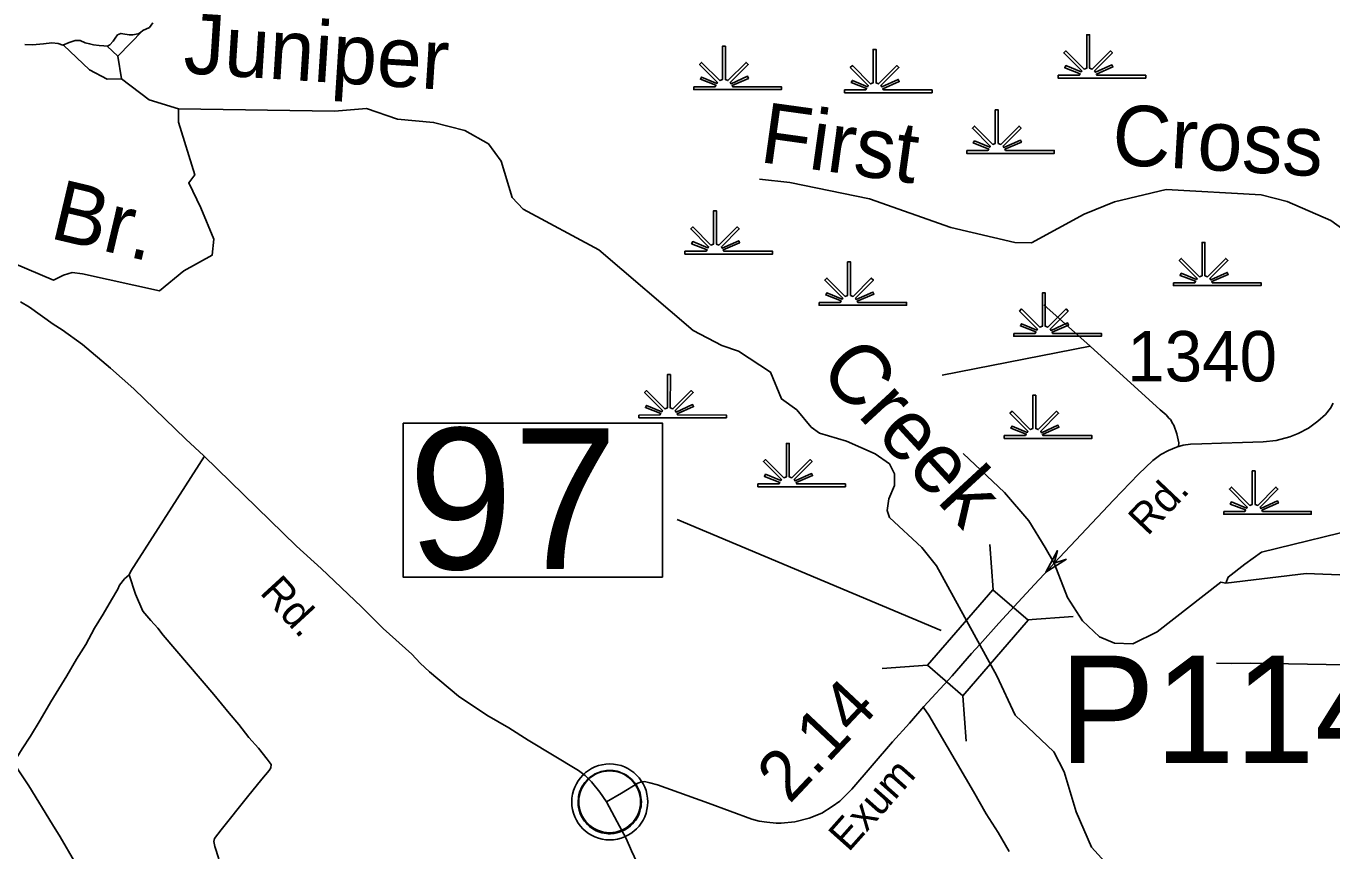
# Model space of a CAD drawing. Extents: x 2104537 to 2336408, y 34176 to 229611.
# Drawn here: x 2173826 to 2186795, y 134278 to 142470 of the extents above; entities that cross this region are included whole.
import ezdxf

# ---------------------------------------------------------------- set-up
doc = ezdxf.new("R2010")
doc.units = 0
for name, color, linetype in [('Exist Boundary Political CountyLine', 7, 'Continuous'), ('Exist Civil Demographics Community CELL', 7, 'Continuous'), ('Exist Hydrographic Creek Single Shore', 7, 'Continuous'), ('Exist Hydrographic Misc Water Feature', 7, 'Continuous'), ('Exist Hydrographic Pond Under 1500 Sq Ft', 7, 'Continuous'), ('Exist Hydrographic Swamp CELL', 7, 'Continuous'), ('Exist Road Non-System Type 51', 7, 'Continuous'), ('Exist Road Primary NC Structure Standard Bridge Number Label', 7, 'Continuous'), ('Exist Road Secondary Mileage Hundredths English Label', 7, 'Continuous'), ('Exist Road Secondary Structure Pipe Attributed CELL', 7, 'Continuous'), ('Exist Road Secondary Structure Pipe Number Label', 7, 'Continuous'), ('Exist Road Secondary Structure Standard Bridge CELL', 7, 'Continuous'), ('Exist Road Secondary Structure Standard Bridge Number Label', 7, 'Continuous'), ('Exist Road Secondary Type 51 Attributed', 7, 'Continuous'), ('Exist Road Secondary Type 51 Label', 7, 'Continuous'), ('Exist Road Secondary Type 51 Number Label', 7, 'Continuous'), ('Old_Level_32', 7, 'Continuous')]:
    doc.layers.add(name, color=color, linetype=linetype)

msp = doc.modelspace()

# ---------------------------------------------------------------- linework, layer by layer
at = {"layer": 'Exist Boundary Political CountyLine'}
msp.add_lwpolyline([(2173813, 142288), (2173888, 142285), (2174000, 142295), (2174081, 142304), (2174144, 142298), (2174191, 142279), (2174253, 142307), (2174312, 142326), (2174362, 142326), (2174412, 142304), (2174456, 142295), (2174494, 142285), (2174553, 142276), (2174597, 142273), (2174634, 142270), (2174659, 142285), (2174690, 142320), (2174712, 142351), (2174734, 142382), (2174768, 142398), (2174787, 142392), (2174850, 142382), (2174884, 142382), (2174940, 142392), (2174962, 142407), (2174984, 142426), (2175050, 142457), (2175084, 142501)], dxfattribs=at)
at = {"layer": 'Exist Civil Demographics Community CELL'}
msp.add_lwpolyline([(2179313, 134814), (2179317, 134836), (2179324, 134863), (2179336, 134892), (2179347, 134914), (2179361, 134937), (2179376, 134958), (2179392, 134975), (2179410, 134994), (2179432, 135012), (2179454, 135027), (2179473, 135038), (2179494, 135048), (2179515, 135057), (2179538, 135065), (2179555, 135069), (2179575, 135072), (2179591, 135075), (2179617, 135076), (2179634, 135076), (2179657, 135075), (2179677, 135072), (2179696, 135068), (2179716, 135062), (2179737, 135054), (2179764, 135043), (2179789, 135029), (2179809, 135014), (2179830, 134998), (2179843, 134986), (2179859, 134968), (2179875, 134950), (2179887, 134931), (2179900, 134911), (2179909, 134890), (2179918, 134870), (2179924, 134850), (2179929, 134832), (2179933, 134808), (2179936, 134789), (2179937, 134765), (2179936, 134742), (2179934, 134719), (2179930, 134697), (2179923, 134673), (2179916, 134649), (2179907, 134629), (2179894, 134605), (2179881, 134584), (2179867, 134565), (2179850, 134546), (2179829, 134526), (2179809, 134510), (2179789, 134496), (2179772, 134486), (2179744, 134473), (2179716, 134462), (2179692, 134456), (2179666, 134451), (2179648, 134449), (2179630, 134448), (2179608, 134448), (2179591, 134450), (2179568, 134453), (2179544, 134458), (2179526, 134463), (2179505, 134471), (2179487, 134478), (2179471, 134487), (2179444, 134504), (2179422, 134521), (2179402, 134539), (2179384, 134558), (2179372, 134574), (2179360, 134591), (2179343, 134619), (2179336, 134633), (2179329, 134649), (2179319, 134682), (2179313, 134710), (2179310, 134731), (2179309, 134756), (2179309, 134775), (2179311, 134801)], close=True, dxfattribs=at)
for centre, radius in [((2179623, 134764), 377), ((2179622, 134765), 307)]:
    msp.add_circle(centre, radius, dxfattribs=at)
at = {"layer": 'Exist Hydrographic Creek Single Shore'}
for points in [[(2173376, 137054), (2173391, 137247), (2173323, 137455), (2173104, 137919), (2173034, 138452), (2173350, 139483), (2173422, 139794), (2173443, 139881), (2173530, 140031), (2173629, 140112), (2173702, 140116), (2174097, 139947), (2174197, 139995), (2174283, 140022), (2174387, 140009), (2175151, 139841), (2175391, 140040), (2175674, 140193), (2175692, 140355), (2175561, 140666), (2175441, 140912), (2175502, 140992), (2175341, 141517), (2175340, 141648)], [(2182869, 137108), (2182722, 137292), (2182403, 137590), (2182378, 137657), (2182394, 137774), (2182452, 137908), (2182451, 138023), (2182400, 138122), (2182258, 138223), (2181974, 138347), (2181707, 138427), (2181624, 138485), (2181481, 138658), (2181330, 138766), (2181221, 139034), (2180903, 139240), (2180736, 139296), (2180452, 139446), (2179514, 140248), (2178762, 140653), (2178653, 140767), (2178543, 141127), (2178417, 141300), (2178183, 141432), (2177874, 141514), (2177515, 141544), (2177207, 141651), (2176890, 141625), (2175340, 141648)], [(2189243, 138521), (2188505, 138548), (2188088, 138622), (2187846, 138712), (2187729, 138829), (2187458, 139543), (2187355, 140093), (2187154, 140274), (2186786, 140540), (2186351, 140729), (2186093, 140793), (2185151, 140847), (2184635, 140726), (2184336, 140601), (2183813, 140316), (2183646, 140322), (2183012, 140469), (2182202, 140754), (2181410, 140917), (2181110, 140949)], [(2185930, 137125), (2186096, 137243), (2187178, 137508), (2187369, 137517), (2187703, 137461), (2188028, 137471), (2188236, 137549), (2188460, 137683), (2188783, 137969), (2188941, 138018)], [(2185305, 133145), (2185254, 133260), (2185010, 133652), (2184407, 134314), (2184255, 134664), (2184136, 135064), (2184035, 135262), (2183650, 135627), (2183468, 136017), (2182869, 137108)], [(2185742, 136938), (2185691, 136946), (2185061, 136453), (2184820, 136333), (2184637, 136340), (2184487, 136405), (2184319, 136563), (2184171, 136793), (2184038, 137134)], [(2185742, 136938), (2185766, 136997), (2185930, 137125)]]:
    msp.add_lwpolyline(points, dxfattribs=at)
at = {"layer": 'Exist Hydrographic Misc Water Feature'}
for points in [[(2174738, 142172), (2174987, 142427)], [(2175340, 141648), (2175048, 141739), (2174772, 141945)], [(2184038, 137134), (2183947, 137291), (2183787, 137557), (2183544, 137837), (2183133, 138226)], [(2185742, 136938), (2186541, 137034), (2187374, 136999), (2187674, 137009), (2188455, 137140)]]:
    msp.add_lwpolyline(points, dxfattribs=at)
at = {"layer": 'Exist Hydrographic Pond Under 1500 Sq Ft'}
msp.add_line((2174772, 141945), (2174738, 142172), dxfattribs=at)
for points in [[(2174772, 141945), (2174630, 141944), (2174455, 142036), (2174198, 142282)], [(2174738, 142172), (2174631, 142270)]]:
    msp.add_lwpolyline(points, dxfattribs=at)
at = {"layer": 'Exist Hydrographic Swamp CELL'}
for points in [[(2184076, 141982), (2184287, 141982), (2184295, 141997), (2184142, 142056), (2184153, 142077), (2184304, 142014), (2184311, 142025), (2184133, 142203), (2184153, 142224), (2184335, 142042), (2184360, 142052), (2184360, 142384), (2184389, 142384), (2184389, 142052), (2184414, 142042), (2184595, 142224), (2184616, 142203), (2184438, 142025), (2184446, 142011), (2184610, 142085), (2184620, 142065), (2184456, 141994), (2184462, 141982), (2184946, 141982), (2184946, 141954), (2184076, 141954)], [(2180458, 141868), (2180669, 141868), (2180677, 141883), (2180524, 141942), (2180535, 141963), (2180686, 141900), (2180693, 141911), (2180515, 142090), (2180535, 142110), (2180717, 141928), (2180742, 141938), (2180742, 142270), (2180771, 142270), (2180771, 141938), (2180796, 141928), (2180977, 142110), (2180998, 142090), (2180820, 141911), (2180828, 141897), (2180992, 141971), (2181001, 141951), (2180838, 141880), (2180844, 141868), (2181328, 141868), (2181328, 141840), (2180458, 141840)], [(2181955, 141836), (2182166, 141837), (2182174, 141851), (2182021, 141910), (2182033, 141931), (2182183, 141868), (2182190, 141880), (2182012, 142058), (2182033, 142078), (2182214, 141896), (2182239, 141906), (2182239, 142238), (2182268, 142238), (2182268, 141906), (2182293, 141896), (2182475, 142078), (2182495, 142058), (2182317, 141880), (2182325, 141865), (2182489, 141940), (2182499, 141919), (2182335, 141848), (2182341, 141837), (2182825, 141836), (2182825, 141808), (2181955, 141808)], [(2183168, 141235), (2183379, 141235), (2183387, 141249), (2183234, 141309), (2183246, 141330), (2183397, 141267), (2183403, 141278), (2183225, 141456), (2183246, 141477), (2183427, 141295), (2183452, 141304), (2183452, 141637), (2183481, 141637), (2183481, 141304), (2183506, 141295), (2183688, 141477), (2183708, 141456), (2183530, 141278), (2183538, 141264), (2183702, 141338), (2183712, 141318), (2183548, 141247), (2183554, 141235), (2184038, 141235), (2184038, 141206), (2183168, 141206)], [(2180370, 140234), (2180581, 140235), (2180589, 140249), (2180436, 140308), (2180447, 140329), (2180598, 140266), (2180604, 140278), (2180427, 140456), (2180447, 140476), (2180628, 140294), (2180654, 140304), (2180654, 140636), (2180683, 140636), (2180683, 140304), (2180708, 140294), (2180889, 140476), (2180910, 140456), (2180732, 140278), (2180740, 140263), (2180904, 140338), (2180913, 140318), (2180749, 140246), (2180756, 140235), (2181240, 140234), (2181240, 140206), (2180370, 140206)], [(2185222, 139920), (2185433, 139921), (2185441, 139935), (2185288, 139994), (2185300, 140015), (2185450, 139952), (2185457, 139964), (2185279, 140142), (2185300, 140162), (2185481, 139980), (2185506, 139990), (2185506, 140322), (2185535, 140322), (2185535, 139990), (2185560, 139980), (2185742, 140162), (2185762, 140142), (2185584, 139964), (2185592, 139949), (2185756, 140024), (2185766, 140004), (2185602, 139932), (2185608, 139921), (2186092, 139920), (2186092, 139892), (2185222, 139892)], [(2181702, 139725), (2181913, 139725), (2181921, 139740), (2181768, 139799), (2181779, 139820), (2181930, 139757), (2181937, 139768), (2181759, 139947), (2181780, 139967), (2181961, 139785), (2181986, 139795), (2181986, 140127), (2182015, 140127), (2182015, 139795), (2182040, 139785), (2182221, 139967), (2182242, 139947), (2182064, 139768), (2182072, 139754), (2182236, 139828), (2182246, 139808), (2182082, 139737), (2182088, 139725), (2182572, 139725), (2182572, 139697), (2181702, 139697)], [(2183636, 139418), (2183847, 139418), (2183855, 139433), (2183702, 139492), (2183713, 139513), (2183864, 139450), (2183871, 139461), (2183693, 139640), (2183714, 139660), (2183895, 139478), (2183920, 139488), (2183920, 139820), (2183949, 139820), (2183949, 139488), (2183974, 139478), (2184155, 139660), (2184176, 139640), (2183998, 139461), (2184006, 139447), (2184170, 139521), (2184180, 139501), (2184016, 139430), (2184022, 139418), (2184506, 139418), (2184506, 139390), (2183636, 139390)], [(2179912, 138607), (2180122, 138608), (2180130, 138622), (2179977, 138681), (2179989, 138702), (2180140, 138639), (2180146, 138651), (2179969, 138829), (2179989, 138849), (2180170, 138667), (2180196, 138677), (2180196, 139009), (2180225, 139009), (2180224, 138677), (2180250, 138667), (2180431, 138849), (2180452, 138829), (2180274, 138651), (2180282, 138636), (2180445, 138711), (2180455, 138690), (2180291, 138619), (2180298, 138608), (2180782, 138607), (2180782, 138579), (2179912, 138579)], [(2183542, 138402), (2183752, 138402), (2183760, 138417), (2183607, 138476), (2183619, 138497), (2183770, 138434), (2183776, 138445), (2183598, 138624), (2183619, 138644), (2183800, 138462), (2183825, 138472), (2183825, 138804), (2183854, 138804), (2183854, 138472), (2183879, 138462), (2184061, 138644), (2184081, 138624), (2183903, 138445), (2183911, 138431), (2184075, 138505), (2184085, 138485), (2183921, 138414), (2183927, 138402), (2184412, 138402), (2184412, 138374), (2183542, 138374)], [(2181094, 137923), (2181304, 137923), (2181312, 137937), (2181159, 137997), (2181171, 138018), (2181322, 137955), (2181328, 137966), (2181150, 138144), (2181171, 138165), (2181352, 137983), (2181377, 137992), (2181377, 138325), (2181406, 138325), (2181406, 137992), (2181432, 137983), (2181613, 138165), (2181633, 138144), (2181456, 137966), (2181464, 137952), (2181627, 138026), (2181637, 138006), (2181473, 137935), (2181480, 137923), (2181964, 137923), (2181964, 137894), (2181094, 137894)], [(2185721, 137649), (2185931, 137650), (2185939, 137664), (2185786, 137723), (2185798, 137744), (2185949, 137681), (2185955, 137693), (2185777, 137871), (2185798, 137891), (2185979, 137709), (2186004, 137719), (2186004, 138051), (2186033, 138051), (2186033, 137719), (2186059, 137709), (2186240, 137891), (2186260, 137871), (2186083, 137693), (2186091, 137678), (2186254, 137753), (2186264, 137733), (2186100, 137661), (2186107, 137650), (2186591, 137649), (2186591, 137621), (2185721, 137621)]]:
    msp.add_lwpolyline(points, close=True, dxfattribs=at)
at = {"layer": 'Exist Road Non-System Type 51'}
for p in [(2183936, 139701), (2182924, 139003)]:
    msp.add_line(p, (2184393, 139292), dxfattribs=at)
for points in [[(2184393, 139292), (2185090, 138658), (2185148, 138608), (2185175, 138576), (2185191, 138562), (2185215, 138519), (2185225, 138507), (2185255, 138421), (2185274, 138329), (2185272, 138297)], [(2174849, 137018), (2174867, 137057), (2175598, 138198)], [(2173707, 135161), (2173788, 135292), (2173870, 135416), (2173967, 135577), (2174073, 135757), (2174230, 136017), (2174326, 136183), (2174418, 136329), (2174505, 136490), (2174593, 136630), (2174673, 136772), (2174737, 136878), (2174754, 136916), (2174804, 136980), (2174849, 137018)], [(2175741, 134198), (2175699, 134320), (2175689, 134370), (2175697, 134400), (2175763, 134488), (2176024, 134814), (2176167, 134991), (2176241, 135077), (2176257, 135103), (2176261, 135135), (2176221, 135189), (2176133, 135297), (2176039, 135405), (2175939, 135532), (2175842, 135646), (2175692, 135832), (2175187, 136421), (2175135, 136489), (2175065, 136565), (2174987, 136657), (2174911, 136826), (2174849, 137018)], [(2185651, 136142), (2185802, 136139), (2185991, 136141), (2186926, 136125), (2187180, 136127), (2187268, 136128), (2187338, 136124), (2187426, 136126), (2187548, 136120)], [(2183590, 134273), (2183480, 134459), (2183362, 134644), (2183236, 134868), (2182792, 135625), (2182740, 135701)], [(2174594, 131391), (2174618, 131466), (2174628, 131525), (2174625, 131575), (2174566, 131846), (2174531, 132052), (2174492, 132482), (2174447, 133142), (2174427, 133336), (2174415, 133534), (2174398, 133714), (2174382, 133880), (2174364, 133994), (2174346, 134088), (2174308, 134171), (2174165, 134417), (2174087, 134539), (2173854, 134924), (2173748, 135082), (2173722, 135126), (2173707, 135161)]]:
    msp.add_lwpolyline(points, dxfattribs=at)
at = {"layer": 'Exist Road Primary NC Structure Standard Bridge Number Label'}
msp.add_lwpolyline([(2177570, 138526), (2180146, 138526), (2180146, 136997), (2177570, 136997)], close=True, dxfattribs=at)
at = {"layer": 'Exist Road Secondary Structure Pipe Attributed CELL'}
msp.add_lwpolyline([(2184161, 137174), (2183954, 137045), (2184069, 137260), (2184038, 137134)], close=True, dxfattribs=at)
at = {"layer": 'Exist Road Secondary Structure Standard Bridge CELL'}
for p, q in [((2183431, 136870), (2183399, 137322)), ((2183773, 136574), (2184225, 136606)), ((2182328, 136090), (2182780, 136122)), ((2183162, 135367), (2183130, 135819))]:
    msp.add_line(p, q, dxfattribs=at)
msp.add_lwpolyline([(2182780, 136122), (2183429, 136872), (2183779, 136568), (2183130, 135819)], close=True, dxfattribs=at)
at = {"layer": 'Exist Road Secondary Structure Standard Bridge Number Label'}
msp.add_line((2182915, 136465), (2180292, 137569), dxfattribs=at)
at = {"layer": 'Exist Road Secondary Type 51 Attributed'}
for points in [[(2173769, 139732), (2173859, 139679), (2174094, 139510), (2174185, 139453), (2174385, 139308), (2174665, 139072), (2174897, 138866), (2175413, 138366), (2175590, 138202), (2176511, 137303), (2176758, 137084), (2177156, 136700), (2177371, 136487), (2177657, 136230), (2177739, 136142), (2177831, 136056), (2178120, 135813), (2178401, 135627), (2178621, 135500), (2178813, 135378), (2179311, 135077), (2179379, 135027), (2179442, 134964), (2179523, 134860), (2179591, 134765)], [(2184038, 137134), (2184627, 137761), (2184874, 138020), (2185018, 138156), (2185097, 138214), (2185174, 138256), (2185251, 138287), (2185319, 138308), (2185390, 138318), (2185504, 138322), (2185698, 138328), (2185906, 138333), (2186114, 138341), (2186241, 138353), (2186378, 138389), (2186461, 138424), (2186563, 138476), (2186657, 138545), (2186732, 138611), (2186782, 138674), (2186807, 138724)], [(2183298, 136326), (2183486, 136540), (2183681, 136747), (2183841, 136922), (2183987, 137080), (2184038, 137134)], [(2179591, 134765), (2179741, 134852), (2179902, 134951), (2179938, 134965), (2179968, 134966), (2180020, 134955), (2180096, 134935), (2180604, 134750), (2181035, 134594), (2181108, 134574), (2181182, 134562), (2181277, 134554), (2181326, 134554), (2181461, 134566), (2181602, 134601), (2181728, 134652), (2181833, 134717), (2181907, 134772), (2182028, 134892), (2182432, 135360), (2182599, 135546), (2182741, 135713), (2183023, 136015), (2183216, 136238), (2183298, 136326)], [(2179915, 134115), (2179838, 134278), (2179786, 134400), (2179698, 134566), (2179591, 134765)]]:
    msp.add_lwpolyline(points, dxfattribs=at)

# ---------------------------------------------------------------- texts
at = {"layer": 'Exist Road Primary NC Structure Standard Bridge Number Label'}
msp.add_text('97', height=1400, dxfattribs=at).set_placement((2177620, 137076))
at = {"layer": 'Exist Road Secondary Mileage Hundredths English Label'}
msp.add_text('2.14', height=500, rotation=46.7533, dxfattribs=at).set_placement((2181408, 134736))
at = {"layer": 'Exist Road Secondary Structure Pipe Number Label'}
msp.add_text('P114', height=1066.3, dxfattribs=at).set_placement((2184087, 135150))
at = {"layer": 'Exist Road Secondary Type 51 Label'}
for s, rotation, p in [('Rd.', 46.5176, (2184964, 137398)), ('Rd.', 312.5718, (2176138, 136838)), ('Exum', 48.3553, (2181995, 134258))]:
    msp.add_text(s, height=300, rotation=rotation, dxfattribs=at).set_placement(p)
at = {"layer": 'Exist Road Secondary Type 51 Number Label'}
msp.add_text('1340', height=500, dxfattribs=at).set_placement((2184763, 138941))
at = {"layer": 'Old_Level_32'}
for s, rotation, p in [('Juniper', 356.33, (2175381, 142003)), ('First', 352.0948, (2181100, 141121)), ('Cross', 356.6971, (2184602, 141096)), ('Br.', 346.6934, (2174047, 140367)), ('Creek', 312.6473, (2181684, 139028))]:
    msp.add_text(s, height=600, rotation=rotation, dxfattribs=at).set_placement(p)

doc.saveas('drawing.dxf')
